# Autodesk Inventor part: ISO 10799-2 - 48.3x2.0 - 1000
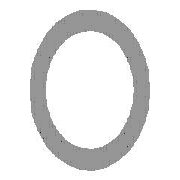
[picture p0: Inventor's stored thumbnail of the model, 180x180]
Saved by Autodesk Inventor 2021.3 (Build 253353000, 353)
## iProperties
IsCustomPart: 1
_CCFamilyMember: 14
_CCFamilyDisplayName: ISO 10799-2 (Profils creux circulaires - Formés à froid) - Aciers de construction - Coupes creuses profilées formées à froid, soudées
_FrameMemberDoc: Frame Member File
_Version: 25.0.0
_GetPNFromCC: 1
Created: 2018-01
Part Number: ISO 10799-2 - 48.3x2.0 - 1000
Material: Acier, doux
Description: Aciers de construction - Coupes creuses profilées formées à froid, soudées
Document SubType Name: Modeling
Standard: ISO
Designer: Fabian Perrée
Standard Revision: First edition 2011-09-15
Standards Organization: ISO
Language: fr-FR
Size Designation: 48.3x2.0
Categories: <MemberInstance><Categories><Category DisplayName="Profilés" InternalName="089c4875-fa83-4c05-b084-43b9cc11f5ed" Mnemonic="GRDR"><CategoryParameter DisplayName=
Stock Number: 48.3x2.0
Density: 7.85 g/cm^3
Appearance: Semi-poli
Mass: 2283.66 g
Surface Area: 2914.93 cm^2
Volume: 290.911 cm^3
G_L: 1000,000 mm
G_W: 48,300 mm
G_H: 48,300 mm
Author: Fabian Perrée
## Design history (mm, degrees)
node "Plan de départ"
node "Plan de fin"
sketch "Esquisse"
  geometry: C1 r 22.15 at (0, 0); C2 r 24.15 at (0, 0); 2 further points
  constraints: 3 coincident, 2 centre point
  dimensions: "d0" = 48.3 diameter of C2 (= G_H); "d1" = 2 radial gap between concentric circles of C2 C1 (= G_T)
extrude "Corps" new body sketch "Esquisse" stored distance "d2" = 1000 (= G_L); taper "d3" = 0 deg
node "Driven Length"
  sketch "Sketch3"
    geometry: L1 (0, 0)-(10, 0) reference
    constraints: 2 end point, 1 horizontal
  workplane "Work Plane3"
  sketch "Sketch4"
    geometry: L1 (-2, 0)-(12, 0) reference; L2 (-2, 1000)-(12, 1000) reference
    dimensions: "d7" = 1000 distance between parallel lines of L1 L2 (derived)
body "Solid1"
other parameters: "G_H" = 48.3 [user parameter; used in 1 equation term], "G_T" = 2 [user parameter; used in 1 equation term], "G_L" = 1000 (= d7) [user parameter; used in 1 equation term], "G_OFFSET_START" = 0 [user parameter; used in 1 equation term], "G_OFFSET_END" = 0 [user parameter; used in 1 equation term], "d4" = 0 (computed from G_OFFSET_START), "d6" = 90 deg, "MAS" = 0.228 [user parameter]
